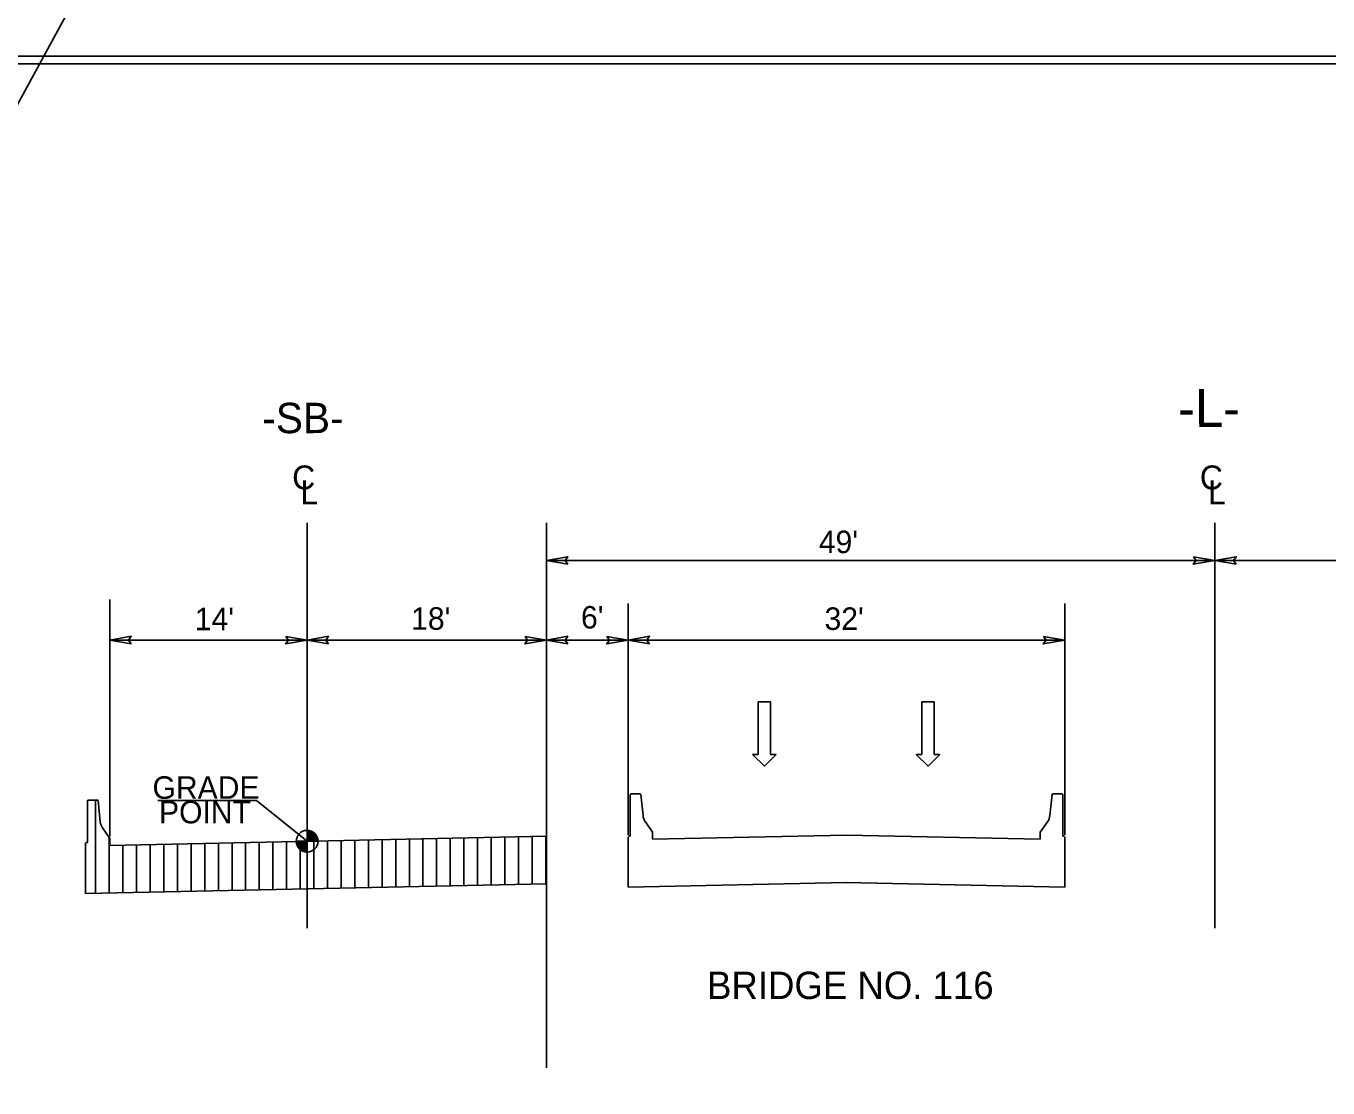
# Model space of a CAD drawing. Extents: x 2241081 to 2251104, y 658534 to 663427.
# Drawn here: x 2245900.8 to 2246330.3, y 660363.9 to 660714.3 of the extents above; entities that cross this region are included whole.
import ezdxf

# ---------------------------------------------------------------- set-up
doc = ezdxf.new("R2010")
doc.units = 0
for name, color, linetype in [('Old_Level_2', 7, 'Continuous'), ('Prop Dimension', 7, 'Continuous'), ('Prop Dimension Text', 7, 'Continuous'), ('Prop Lane Arrow CELL', 7, 'Continuous'), ('Prop Roadway Bridge', 7, 'Continuous'), ('Sheet Plan CELL', 7, 'Continuous'), ('Sheet Plot Border Inside CELL', 7, 'Continuous'), ('Typical Grade Point Symbol CELL', 7, 'Continuous'), ('Typical Terminator CELL', 7, 'Continuous'), ('Typical Text Centerline CELL', 7, 'Continuous'), ('Typical Text Grade Point CELL', 7, 'Continuous')]:
    doc.layers.add(name, color=color, linetype=linetype)

msp = doc.modelspace()

# ---------------------------------------------------------------- linework, layer by layer
at = {"layer": 'Old_Level_2'}
msp.add_line((2245215.42, 659438.44), (2247357.78, 663362.06), dxfattribs=at)
at = {"layer": 'Prop Dimension'}
msp.add_line((2245928.42, 660446.91), (2245928.42, 660525.01), dxfattribs=at)
at = {"layer": 'Prop Dimension Text'}
for p, q in [((2246072.42, 660370.49), (2246072.42, 660550.34)), ((2246072.42, 660537.91), (2246292.92, 660537.91)), ((2246531.42, 660537.91), (2246292.92, 660537.91)), ((2246099.42, 660447.28), (2246099.42, 660523.7)), ((2246243.42, 660447.28), (2246243.42, 660523.7)), ((2245928.42, 660511.65), (2245993.47, 660511.65)), ((2245993.47, 660511.65), (2246072.42, 660511.65)), ((2246072.42, 660511.65), (2246099.42, 660511.65)), ((2246243.42, 660511.65), (2246099.42, 660511.65)), ((2245923.72, 660428.15), (2245923.72, 660458.86)), ((2246063.22, 660431.05), (2246063.22, 660446.72)), ((2246067.72, 660431.15), (2246067.72, 660446.81)), ((2246072.22, 660431.24), (2246072.22, 660446.9)), ((2245928.22, 660428.25), (2245928.22, 660446.51)), ((2245932.72, 660428.34), (2245932.72, 660444)), ((2245937.22, 660428.43), (2245937.22, 660444.1)), ((2245941.72, 660428.53), (2245941.72, 660444.19)), ((2245946.22, 660428.62), (2245946.22, 660444.28)), ((2245950.72, 660428.71), (2245950.72, 660444.38)), ((2245955.22, 660428.81), (2245955.22, 660444.47)), ((2245959.72, 660428.9), (2245959.72, 660444.56)), ((2245964.22, 660428.99), (2245964.22, 660444.66)), ((2245968.72, 660429.09), (2245968.72, 660444.75)), ((2245973.22, 660429.18), (2245973.22, 660444.85)), ((2245977.72, 660429.28), (2245977.72, 660444.94)), ((2245982.22, 660429.37), (2245982.22, 660445.03)), ((2245986.72, 660429.46), (2245986.72, 660445.13)), ((2245991.22, 660429.56), (2245991.22, 660445.22)), ((2245995.72, 660429.65), (2245995.72, 660445.31)), ((2246000.22, 660429.74), (2246000.22, 660445.41)), ((2246004.72, 660429.84), (2246004.72, 660445.5)), ((2246009.22, 660429.93), (2246009.22, 660445.59)), ((2246013.72, 660430.02), (2246013.72, 660445.69)), ((2246018.22, 660430.12), (2246018.22, 660445.78)), ((2246022.72, 660430.21), (2246022.72, 660445.88)), ((2246027.22, 660430.3), (2246027.22, 660445.97)), ((2246031.72, 660430.4), (2246031.72, 660446.06)), ((2246036.22, 660430.49), (2246036.22, 660446.16)), ((2246040.72, 660430.59), (2246040.72, 660446.25)), ((2246045.22, 660430.68), (2246045.22, 660446.34)), ((2246049.72, 660430.77), (2246049.72, 660446.44)), ((2246054.22, 660430.87), (2246054.22, 660446.53)), ((2246058.72, 660430.96), (2246058.72, 660446.62))]:
    msp.add_line(p, q, dxfattribs=at)
at = {"layer": 'Prop Lane Arrow CELL'}
for p, q in [((2246142.31, 660473.92), (2246142.31, 660491.29)), ((2246142.31, 660491.29), (2246146.4, 660491.29)), ((2246146.4, 660491.29), (2246146.4, 660473.92)), ((2246196.31, 660473.92), (2246196.31, 660491.29)), ((2246196.31, 660491.29), (2246200.4, 660491.29)), ((2246200.4, 660491.29), (2246200.4, 660473.92)), ((2246144.42, 660470.01), (2246140.45, 660473.92)), ((2246140.45, 660473.92), (2246142.31, 660473.92)), ((2246148.26, 660473.92), (2246144.42, 660470.01)), ((2246146.4, 660473.92), (2246148.26, 660473.92)), ((2246198.42, 660470.01), (2246194.45, 660473.92)), ((2246194.45, 660473.92), (2246196.31, 660473.92)), ((2246202.26, 660473.92), (2246198.42, 660470.01)), ((2246200.4, 660473.92), (2246202.26, 660473.92))]:
    msp.add_line(p, q, dxfattribs=at)
at = {"layer": 'Prop Roadway Bridge'}
for p, q in [((2246100.24, 660460.9), (2246100.07, 660460.73)), ((2246100.07, 660460.73), (2246100.07, 660446.96)), ((2246103.39, 660460.9), (2246100.24, 660460.9)), ((2246103.58, 660460.71), (2246103.39, 660460.9)), ((2246104.31, 660453.74), (2246103.58, 660460.71)), ((2246238.53, 660453.74), (2246239.26, 660460.71)), ((2246239.26, 660460.71), (2246239.44, 660460.9)), ((2246239.44, 660460.9), (2246242.6, 660460.9)), ((2246242.6, 660460.9), (2246242.77, 660460.73)), ((2246242.77, 660460.73), (2246242.77, 660446.96)), ((2245921.18, 660458.86), (2245921.01, 660458.7)), ((2245921.01, 660458.7), (2245921.01, 660444.92)), ((2245924.33, 660458.86), (2245921.18, 660458.86)), ((2245924.52, 660458.68), (2245924.33, 660458.86)), ((2245925.25, 660451.7), (2245924.52, 660458.68)), ((2246107.48, 660448.27), (2246105.07, 660451.7)), ((2246235.36, 660448.27), (2246237.76, 660451.7)), ((2245928.42, 660446.23), (2245926.02, 660449.66)), ((2246072.42, 660446.91), (2245928.42, 660443.91)), ((2246099.75, 660446.96), (2246099.42, 660446.63)), ((2246100.07, 660446.96), (2246099.75, 660446.96)), ((2246107.48, 660445.95), (2246107.48, 660448.27)), ((2246171.42, 660447.28), (2246107.48, 660445.95)), ((2246171.42, 660447.28), (2246235.36, 660445.95)), ((2246235.36, 660445.95), (2246235.36, 660448.27)), ((2246242.77, 660446.96), (2246243.09, 660446.96)), ((2246243.09, 660446.96), (2246243.42, 660446.63)), ((2245920.69, 660444.92), (2245920.36, 660444.6)), ((2245920.36, 660444.6), (2245920.36, 660442.31)), ((2245921.01, 660444.92), (2245920.69, 660444.92)), ((2245928.42, 660443.91), (2245928.42, 660446.23)), ((2246099.42, 660446.63), (2246099.42, 660444.35)), ((2246099.42, 660444.35), (2246099.42, 660430.12)), ((2246243.42, 660446.63), (2246243.42, 660444.35)), ((2246243.42, 660444.35), (2246243.42, 660430.12)), ((2245920.36, 660442.31), (2245920.36, 660428.08)), ((2246072.42, 660431.24), (2245920.36, 660428.08)), ((2246171.42, 660431.62), (2246099.42, 660430.12)), ((2246171.09, 660431.62), (2246243.42, 660430.12))]:
    msp.add_line(p, q, dxfattribs=at)
for centre, start, end in [((2245929.58, 660452.16), 186.011, 214.9912), ((2246108.64, 660454.2), 186.011, 214.9912), ((2246234.2, 660454.2), 325.0086, 353.9889)]:
    msp.add_arc(centre, 4.36, start, end, dxfattribs=at)
at = {"layer": 'Sheet Plan CELL'}
for points in [[(2245563.81, 659651.78), (2245563.79, 660701.76), (2246863.77, 660701.79), (2246863.79, 660551.73), (2247063.82, 660551.72), (2247063.82, 659651.78)], [(2247063.85, 660701.78), (2245563.81, 660701.78), (2245563.81, 659651.78), (2247063.82, 659651.78)]]:
    msp.add_lwpolyline(points, close=True, dxfattribs=at)
at = {"layer": 'Sheet Plot Border Inside CELL'}
msp.add_lwpolyline([(2245410.32, 659649.27), (2247076.31, 659649.28), (2247076.32, 660704.27), (2245410.32, 660704.27)], close=True, dxfattribs=at)
at = {"layer": 'Typical Grade Point Symbol CELL'}
for p, q in [((2245993.47, 660445.27), (2245976.78, 660458.72)), ((2245993.48, 660448.85), (2245993.47, 660445.27)), ((2245993.47, 660445.27), (2245993.48, 660448.85)), ((2245989.89, 660445.27), (2245993.47, 660445.27)), ((2245993.47, 660445.27), (2245993.47, 660441.69)), ((2245997.05, 660445.27), (2245993.47, 660445.27))]:
    msp.add_line(p, q, dxfattribs=at)
for points in [[(2245993.53, 660445.27), (2245993.53, 660448.85), (2245993.53, 660448.85)], [(2245993.6, 660445.27), (2245993.6, 660448.85)], [(2245993.67, 660445.27), (2245993.67, 660448.84)], [(2245993.74, 660445.27), (2245993.74, 660448.84)], [(2245993.81, 660445.27), (2245993.81, 660448.83)], [(2245993.88, 660445.27), (2245993.88, 660448.82)], [(2245993.96, 660445.27), (2245993.96, 660448.82)], [(2245994.03, 660445.27), (2245994.03, 660448.8)], [(2245994.1, 660445.27), (2245994.1, 660448.79)], [(2245994.17, 660445.27), (2245994.17, 660448.78)], [(2245994.24, 660445.27), (2245994.24, 660448.76)], [(2245994.31, 660445.27), (2245994.31, 660448.74)], [(2245994.39, 660445.27), (2245994.39, 660448.73)], [(2245994.46, 660445.27), (2245994.46, 660448.7)], [(2245994.53, 660445.27), (2245994.53, 660448.69)], [(2245994.6, 660445.27), (2245994.6, 660448.66)], [(2245994.67, 660445.27), (2245994.67, 660448.64)], [(2245994.74, 660445.27), (2245994.74, 660448.62)], [(2245994.81, 660445.27), (2245994.81, 660448.58)], [(2245994.89, 660445.27), (2245994.89, 660448.55)], [(2245994.96, 660445.27), (2245994.96, 660448.52)], [(2245995.03, 660445.27), (2245995.03, 660448.49)], [(2245995.1, 660445.27), (2245995.1, 660448.46)], [(2245995.17, 660445.27), (2245995.17, 660448.42)], [(2245995.24, 660445.27), (2245995.24, 660448.38)], [(2245995.32, 660445.27), (2245995.32, 660448.34)], [(2245995.39, 660445.27), (2245995.39, 660448.29)], [(2245995.46, 660445.27), (2245995.46, 660448.24)], [(2245995.53, 660445.27), (2245995.53, 660448.19)], [(2245995.6, 660445.27), (2245995.6, 660448.15)], [(2245995.67, 660445.27), (2245995.67, 660448.09)], [(2245995.75, 660445.27), (2245995.75, 660448.04)], [(2245995.82, 660445.27), (2245995.82, 660447.97)], [(2245995.89, 660445.27), (2245995.89, 660447.91)], [(2245995.96, 660445.27), (2245995.96, 660447.84)], [(2245996.03, 660445.27), (2245996.03, 660447.77)], [(2245996.1, 660445.27), (2245996.1, 660447.69)], [(2245996.18, 660445.27), (2245996.18, 660447.61)], [(2245996.25, 660445.27), (2245996.25, 660447.53)], [(2245996.32, 660445.27), (2245996.32, 660447.44)], [(2245996.39, 660445.27), (2245996.39, 660447.34)], [(2245996.46, 660445.27), (2245996.46, 660447.24)], [(2245996.53, 660445.27), (2245996.53, 660447.13)], [(2245996.61, 660445.27), (2245996.61, 660447)], [(2245996.68, 660445.27), (2245996.68, 660446.87)], [(2245996.75, 660445.27), (2245996.75, 660446.71)], [(2245989.93, 660444.76), (2245989.93, 660445.27)], [(2245990, 660444.39), (2245990, 660445.27)], [(2245990.07, 660444.14), (2245990.07, 660445.27)], [(2245990.14, 660443.95), (2245990.14, 660445.27)], [(2245990.22, 660443.78), (2245990.22, 660445.27)], [(2245990.29, 660443.63), (2245990.29, 660445.27)], [(2245990.36, 660443.5), (2245990.36, 660445.27)], [(2245990.43, 660443.38), (2245990.43, 660445.27)], [(2245990.5, 660443.27), (2245990.5, 660445.27)], [(2245990.57, 660443.17), (2245990.57, 660445.27)], [(2245990.65, 660443.07), (2245990.65, 660445.27)], [(2245990.72, 660442.98), (2245990.72, 660445.27)], [(2245990.79, 660442.9), (2245990.79, 660445.27)], [(2245990.86, 660442.82), (2245990.86, 660445.27)], [(2245990.93, 660442.74), (2245990.93, 660445.27)], [(2245991, 660442.67), (2245991, 660445.27)], [(2245991.08, 660442.61), (2245991.08, 660445.27)], [(2245991.15, 660442.55), (2245991.15, 660445.27)], [(2245991.22, 660442.48), (2245991.22, 660445.27)], [(2245991.29, 660442.43), (2245991.29, 660445.27)], [(2245991.36, 660442.38), (2245991.36, 660445.27)], [(2245991.43, 660442.32), (2245991.43, 660445.27)], [(2245991.5, 660442.27), (2245991.5, 660445.27)], [(2245991.58, 660442.23), (2245991.58, 660445.27)], [(2245991.65, 660442.19), (2245991.65, 660445.27)], [(2245991.72, 660442.15), (2245991.72, 660445.27)], [(2245991.79, 660442.11), (2245991.79, 660445.27)], [(2245991.86, 660442.07), (2245991.86, 660445.27)], [(2245991.93, 660442.04), (2245991.93, 660445.27)], [(2245992.01, 660442), (2245992.01, 660445.27)], [(2245992.08, 660441.97), (2245992.08, 660445.27)], [(2245992.15, 660441.94), (2245992.15, 660445.27)], [(2245992.22, 660441.91), (2245992.22, 660445.27)], [(2245992.29, 660441.88), (2245992.29, 660445.27)], [(2245992.36, 660441.86), (2245992.36, 660445.27)], [(2245992.44, 660441.84), (2245992.44, 660445.27)], [(2245992.51, 660441.82), (2245992.51, 660445.27)], [(2245992.58, 660441.8), (2245992.58, 660445.27)], [(2245992.65, 660441.78), (2245992.65, 660445.27)], [(2245992.72, 660441.77), (2245992.72, 660445.27)], [(2245992.79, 660441.75), (2245992.79, 660445.27)], [(2245992.87, 660441.73), (2245992.87, 660445.27)], [(2245992.94, 660441.73), (2245992.94, 660445.27)], [(2245993.01, 660441.72), (2245993.01, 660445.27)], [(2245993.08, 660441.71), (2245993.08, 660445.27)], [(2245993.15, 660441.7), (2245993.15, 660445.27)], [(2245993.22, 660441.69), (2245993.22, 660445.27)], [(2245993.29, 660441.69), (2245993.29, 660445.27)], [(2245993.37, 660441.69), (2245993.37, 660445.27)], [(2245993.44, 660441.69), (2245993.44, 660441.69), (2245993.44, 660445.27)], [(2245996.82, 660445.27), (2245996.82, 660446.55)], [(2245996.89, 660445.27), (2245996.89, 660446.33)], [(2245996.96, 660445.27), (2245996.96, 660446.08)], [(2245997.03, 660445.27), (2245997.03, 660445.66)]]:
    msp.add_lwpolyline(points, dxfattribs=at)
msp.add_circle((2245993.47, 660445.27), 3.58, dxfattribs=at)
for start, end in [(359.9905, 89.9905), (179.9905, 269.9905)]:
    msp.add_arc((2245993.47, 660445.27), 3.58, start, end, dxfattribs=at)
at = {"layer": 'Typical Terminator CELL'}
for points in [[(2246079.45, 660536.7), (2246072.42, 660537.91), (2246079.49, 660539.16), (2246078.59, 660537.91)], [(2246285.89, 660539.12), (2246292.92, 660537.91), (2246285.85, 660536.66), (2246286.75, 660537.91)], [(2246299.95, 660536.7), (2246292.92, 660537.91), (2246299.99, 660539.16), (2246299.09, 660537.91)], [(2245935.45, 660510.44), (2245928.42, 660511.65), (2245935.49, 660512.9), (2245934.59, 660511.65)], [(2245986.44, 660512.86), (2245993.47, 660511.65), (2245986.4, 660510.4), (2245987.3, 660511.65)], [(2246000.5, 660510.44), (2245993.47, 660511.65), (2246000.54, 660512.9), (2245999.64, 660511.65)], [(2246065.39, 660512.86), (2246072.42, 660511.65), (2246065.35, 660510.4), (2246066.25, 660511.65)], [(2246079.45, 660510.44), (2246072.42, 660511.65), (2246079.49, 660512.9), (2246078.59, 660511.65)], [(2246092.39, 660512.86), (2246099.42, 660511.65), (2246092.35, 660510.4), (2246093.25, 660511.65)], [(2246106.45, 660510.44), (2246099.42, 660511.65), (2246106.49, 660512.9), (2246105.59, 660511.65)], [(2246236.39, 660512.86), (2246243.42, 660511.65), (2246236.35, 660510.4), (2246237.25, 660511.65)]]:
    msp.add_lwpolyline(points, close=True, dxfattribs=at)
at = {"layer": 'Typical Text Centerline CELL'}
for p, q in [((2245993.47, 660550.34), (2245993.47, 660416.64)), ((2246292.92, 660416.64), (2246292.92, 660550.34))]:
    msp.add_line(p, q, dxfattribs=at)
at = {"layer": 'Typical Text Grade Point CELL'}
msp.add_line((2245976.78, 660458.72), (2245944.27, 660458.72), dxfattribs=at)

# ---------------------------------------------------------------- texts
at = {"layer": 'Prop Dimension Text'}
for s, height, rotation, p in [('-L-', 12.5, 0.0349, (2246280.84, 660581.97)), ('-SB-', 10.024, 0.0349, (2245978.72, 660579.92)), ("49'", 7.425, 359.9999, (2246162.3, 660540.34)), ("14'", 7.425, 359.9999, (2245956.44, 660514.92)), ("18'", 7.425, 359.9999, (2246027.81, 660515.06)), ("6'", 7.425, 359.9999, (2246083.85, 660515.47)), ("32'", 7.425, 359.9999, (2246164.19, 660515.01)), ('BRIDGE NO. 116', 9.0214, 359.9999, (2246125.44, 660393.23))]:
    msp.add_text(s, height=height, rotation=rotation, dxfattribs=at).set_placement(p)
at = {"layer": 'Typical Text Centerline CELL'}
for s, rotation, p in [('C', 359.9999, (2245988.56, 660561.39)), ('C', 359.9999, (2246288, 660561.39)), ('L', 359.9468, (2245991.28, 660556.44)), ('L', 359.9468, (2246290.73, 660556.44))]:
    msp.add_text(s, height=7.88, rotation=rotation, dxfattribs=at).set_placement(p)
at = {"layer": 'Typical Text Grade Point CELL'}
for s, p in [('GRADE', (2245942.48, 660459.28)), ('POINT', (2245944.63, 660451.18))]:
    msp.add_text(s, height=7.425, rotation=359.9999, dxfattribs=at).set_placement(p)

doc.saveas('drawing.dxf')
